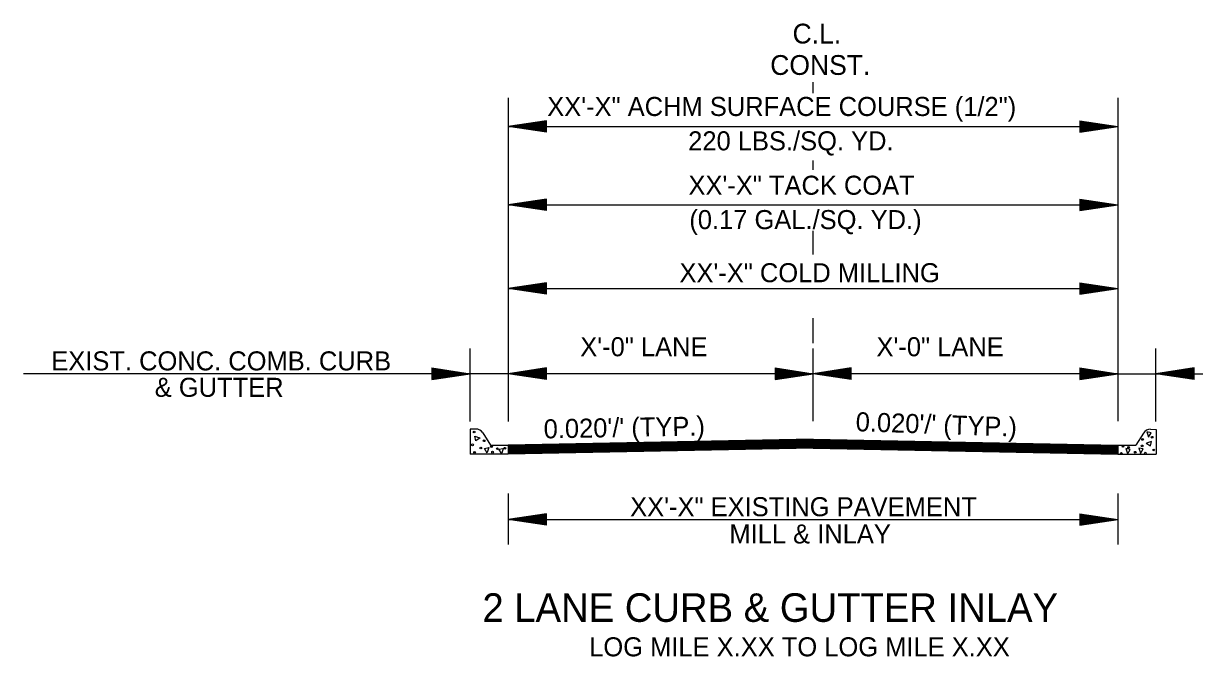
# Model space of a CAD drawing. Extents: x 542112 to 1930787, y -1968972 to 596640.
# Drawn here: x 546672.7 to 547133.6, y -1955910.7 to -1955661.3 of the extents above; entities that cross this region are included whole.
import ezdxf

# ---------------------------------------------------------------- set-up
doc = ezdxf.new("R2010")
doc.units = 0
doc.layers.add('R_Draft', color=7, linetype='Continuous')

msp = doc.modelspace()

# ---------------------------------------------------------------- linework, layer by layer
at = {"layer": 'R_Draft'}
for p, q in [((546983.53, -1955688.78), (546983.53, -1955684.37)), ((546863.53, -1955690.63), (546863.53, -1955818.05)), ((546878.53, -1955699.64), (546863.53, -1955701.89)), ((546863.53, -1955701.89), (547103.46, -1955701.89)), ((546878.53, -1955704.14), (546863.53, -1955701.89)), ((546878.53, -1955700.01), (546866.03, -1955701.89)), ((546878.53, -1955703.76), (546866.03, -1955701.89)), ((546878.53, -1955700.39), (546868.61, -1955701.89)), ((546878.53, -1955703.38), (546868.61, -1955701.89)), ((546878.53, -1955700.77), (546871.11, -1955701.89)), ((546878.53, -1955703), (546871.11, -1955701.89)), ((546878.53, -1955701.15), (546873.65, -1955701.89)), ((546878.53, -1955702.61), (546873.65, -1955701.89)), ((546878.53, -1955701.53), (546876.16, -1955701.89)), ((546878.53, -1955702.24), (546876.16, -1955701.89)), ((546878.53, -1955704.14), (546878.53, -1955699.64)), ((547088.46, -1955699.64), (547103.46, -1955701.89)), ((547088.46, -1955699.64), (547088.46, -1955704.14)), ((547088.46, -1955700.01), (547100.95, -1955701.89)), ((547088.46, -1955700.39), (547098.37, -1955701.89)), ((547088.46, -1955700.77), (547095.87, -1955701.89)), ((547088.46, -1955701.16), (547093.33, -1955701.89)), ((547088.46, -1955701.53), (547090.83, -1955701.89)), ((547088.46, -1955704.14), (547103.46, -1955701.89)), ((547088.46, -1955702.62), (547093.33, -1955701.89)), ((547088.46, -1955703.38), (547098.37, -1955701.89)), ((547088.46, -1955703.76), (547100.95, -1955701.89)), ((547088.46, -1955703), (547095.87, -1955701.89)), ((547088.46, -1955702.24), (547090.83, -1955701.89)), ((546983.53, -1955718.91), (546983.53, -1955715.24)), ((546878.53, -1955730.51), (546863.53, -1955732.76)), ((546878.53, -1955735.01), (546878.53, -1955730.51)), ((547088.46, -1955730.51), (547103.46, -1955732.76)), ((547088.46, -1955730.51), (547088.46, -1955735.01)), ((546863.53, -1955732.76), (547103.46, -1955732.76)), ((546878.53, -1955735.01), (546863.53, -1955732.76)), ((546878.53, -1955730.88), (546866.03, -1955732.76)), ((546878.53, -1955734.63), (546866.03, -1955732.76)), ((546878.53, -1955731.26), (546868.61, -1955732.76)), ((546878.53, -1955734.25), (546868.61, -1955732.76)), ((546878.53, -1955731.64), (546871.11, -1955732.76)), ((546878.53, -1955733.87), (546871.11, -1955732.76)), ((546878.53, -1955732.02), (546873.65, -1955732.76)), ((546878.53, -1955733.48), (546873.65, -1955732.76)), ((546878.53, -1955732.4), (546876.16, -1955732.76)), ((546878.53, -1955733.11), (546876.16, -1955732.76)), ((547088.46, -1955730.88), (547100.95, -1955732.76)), ((547088.46, -1955731.26), (547098.37, -1955732.76)), ((547088.46, -1955731.64), (547095.87, -1955732.76)), ((547088.46, -1955732.03), (547093.33, -1955732.76)), ((547088.46, -1955732.4), (547090.83, -1955732.76)), ((547088.46, -1955735.01), (547103.46, -1955732.76)), ((547088.46, -1955733.49), (547093.33, -1955732.76)), ((547088.46, -1955734.25), (547098.37, -1955732.76)), ((547088.46, -1955734.63), (547100.95, -1955732.76)), ((547088.46, -1955733.87), (547095.87, -1955732.76)), ((547088.46, -1955733.11), (547090.83, -1955732.76)), ((546983.53, -1955752.27), (546983.53, -1955742.97)), ((546878.53, -1955763.44), (546863.53, -1955765.69)), ((546863.53, -1955765.69), (547103.46, -1955765.69)), ((546878.53, -1955767.94), (546863.53, -1955765.69)), ((546878.53, -1955763.81), (546866.03, -1955765.69)), ((546878.53, -1955767.56), (546866.03, -1955765.69)), ((546878.53, -1955764.19), (546868.61, -1955765.69)), ((546878.53, -1955767.18), (546868.61, -1955765.69)), ((546878.53, -1955764.57), (546871.11, -1955765.69)), ((546878.53, -1955766.8), (546871.11, -1955765.69)), ((546878.53, -1955764.95), (546873.65, -1955765.69)), ((546878.53, -1955766.41), (546873.65, -1955765.69)), ((546878.53, -1955765.33), (546876.16, -1955765.69)), ((546878.53, -1955766.04), (546876.16, -1955765.69)), ((546878.53, -1955767.94), (546878.53, -1955763.44)), ((547088.46, -1955763.44), (547103.46, -1955765.69)), ((547088.46, -1955763.44), (547088.46, -1955767.94)), ((547088.46, -1955763.81), (547100.95, -1955765.69)), ((547088.46, -1955764.19), (547098.37, -1955765.69)), ((547088.46, -1955764.57), (547095.87, -1955765.69)), ((547088.46, -1955764.96), (547093.33, -1955765.69)), ((547088.46, -1955765.33), (547090.83, -1955765.69)), ((547088.46, -1955767.94), (547103.46, -1955765.69)), ((547088.46, -1955766.42), (547093.33, -1955765.69)), ((547088.46, -1955767.18), (547098.37, -1955765.69)), ((547088.46, -1955767.56), (547100.95, -1955765.69)), ((547088.46, -1955766.8), (547095.87, -1955765.69)), ((547088.46, -1955766.04), (547090.83, -1955765.69)), ((546983.53, -1955787.21), (546983.53, -1955777.34)), ((546848.53, -1955818.05), (546848.53, -1955789.33)), ((546983.53, -1955817.88), (546983.53, -1955789.33)), ((547118.46, -1955818.05), (547118.46, -1955789.33)), ((546863.53, -1955799.22), (546672.72, -1955799.22)), ((546833.52, -1955796.97), (546848.52, -1955799.22)), ((546833.52, -1955796.97), (546833.52, -1955801.47)), ((546833.52, -1955797.35), (546846.01, -1955799.22)), ((546833.52, -1955797.73), (546843.43, -1955799.22)), ((546833.52, -1955798.11), (546840.94, -1955799.22)), ((546833.52, -1955798.5), (546838.39, -1955799.22)), ((546833.52, -1955798.87), (546835.89, -1955799.22)), ((546833.52, -1955801.47), (546848.52, -1955799.22)), ((546833.52, -1955799.96), (546838.39, -1955799.22)), ((546833.52, -1955800.72), (546843.43, -1955799.22)), ((546833.52, -1955801.1), (546846.01, -1955799.22)), ((546833.52, -1955800.34), (546840.94, -1955799.22)), ((546833.52, -1955799.58), (546835.89, -1955799.22)), ((546878.53, -1955796.97), (546863.53, -1955799.22)), ((546983.53, -1955799.22), (546863.53, -1955799.22)), ((546878.53, -1955801.47), (546863.53, -1955799.22)), ((546878.53, -1955797.35), (546866.03, -1955799.22)), ((546878.53, -1955801.1), (546866.03, -1955799.22)), ((546878.53, -1955797.73), (546868.61, -1955799.22)), ((546878.53, -1955800.72), (546868.61, -1955799.22)), ((546878.53, -1955798.11), (546871.11, -1955799.22)), ((546878.53, -1955800.34), (546871.11, -1955799.22)), ((546878.53, -1955798.49), (546873.65, -1955799.22)), ((546878.53, -1955799.95), (546873.65, -1955799.22)), ((546878.53, -1955798.87), (546876.16, -1955799.22)), ((546878.53, -1955799.58), (546876.16, -1955799.22)), ((546878.53, -1955801.47), (546878.53, -1955796.97)), ((546968.53, -1955796.97), (546983.53, -1955799.22)), ((546968.53, -1955796.97), (546968.53, -1955801.47)), ((546968.53, -1955797.35), (546981.02, -1955799.22)), ((546968.53, -1955797.73), (546978.44, -1955799.22)), ((546968.53, -1955798.11), (546975.95, -1955799.22)), ((546968.53, -1955798.5), (546973.4, -1955799.22)), ((546968.53, -1955798.87), (546970.9, -1955799.22)), ((546968.53, -1955801.47), (546983.53, -1955799.22)), ((546968.53, -1955799.96), (546973.4, -1955799.22)), ((546968.53, -1955800.72), (546978.44, -1955799.22)), ((546968.53, -1955801.1), (546981.02, -1955799.22)), ((546968.53, -1955800.34), (546975.95, -1955799.22)), ((546968.53, -1955799.58), (546970.9, -1955799.22)), ((546998.53, -1955796.97), (546983.53, -1955799.22)), ((547103.46, -1955799.22), (546983.53, -1955799.22)), ((546998.53, -1955801.47), (546983.53, -1955799.22)), ((546998.53, -1955797.35), (546986.03, -1955799.22)), ((546998.53, -1955801.1), (546986.03, -1955799.22)), ((546998.53, -1955797.73), (546988.61, -1955799.22)), ((546998.53, -1955800.72), (546988.61, -1955799.22)), ((546998.53, -1955798.11), (546991.11, -1955799.22)), ((546998.53, -1955800.34), (546991.11, -1955799.22)), ((546998.53, -1955798.49), (546993.65, -1955799.22)), ((546998.53, -1955799.95), (546993.65, -1955799.22)), ((546998.53, -1955798.87), (546996.16, -1955799.22)), ((546998.53, -1955799.58), (546996.16, -1955799.22)), ((546998.53, -1955801.47), (546998.53, -1955796.97)), ((547088.46, -1955796.97), (547103.46, -1955799.22)), ((547088.46, -1955796.97), (547088.46, -1955801.47)), ((547088.46, -1955797.35), (547100.95, -1955799.22)), ((547088.46, -1955797.73), (547098.37, -1955799.22)), ((547088.46, -1955798.11), (547095.87, -1955799.22)), ((547088.46, -1955798.5), (547093.33, -1955799.22)), ((547088.46, -1955798.87), (547090.83, -1955799.22)), ((547088.46, -1955801.47), (547103.46, -1955799.22)), ((547088.46, -1955799.96), (547093.33, -1955799.22)), ((547088.46, -1955800.72), (547098.37, -1955799.22)), ((547088.46, -1955801.1), (547100.95, -1955799.22)), ((547088.46, -1955800.34), (547095.87, -1955799.22)), ((547088.46, -1955799.58), (547090.83, -1955799.22)), ((547103.46, -1955799.22), (547300.14, -1955799.22)), ((547133.46, -1955796.97), (547118.46, -1955799.22)), ((547133.46, -1955801.47), (547118.46, -1955799.22)), ((547133.46, -1955797.35), (547120.96, -1955799.22)), ((547133.46, -1955801.1), (547120.96, -1955799.22)), ((547133.46, -1955797.73), (547123.54, -1955799.22)), ((547133.46, -1955800.72), (547123.54, -1955799.22)), ((547133.46, -1955798.11), (547126.04, -1955799.22)), ((547133.46, -1955800.34), (547126.04, -1955799.22)), ((547133.46, -1955798.49), (547128.58, -1955799.22)), ((547133.46, -1955799.95), (547128.58, -1955799.22)), ((547133.46, -1955798.87), (547131.09, -1955799.22)), ((547133.46, -1955799.58), (547131.09, -1955799.22)), ((547133.46, -1955801.47), (547133.46, -1955796.97)), ((546850.69, -1955821.04), (546848.53, -1955821.08)), ((546848.53, -1955821.08), (546848.53, -1955830.93)), ((546853.51, -1955822.54), (546856.61, -1955827.44)), ((547113.5, -1955822.63), (547110.47, -1955827.43)), ((547116.32, -1955821.13), (547118.48, -1955821.17)), ((547118.48, -1955821.17), (547118.48, -1955830.93)), ((546983.53, -1955825.04), (546863.53, -1955827.44)), ((546983.53, -1955825.34), (546863.53, -1955827.74)), ((546983.53, -1955825.64), (546863.53, -1955828.04)), ((546983.53, -1955825.94), (546863.53, -1955828.34)), ((546983.53, -1955826.24), (546863.53, -1955828.64)), ((546983.53, -1955826.54), (546863.53, -1955828.94)), ((546983.53, -1955826.84), (546863.53, -1955829.24)), ((546983.53, -1955827.14), (546863.53, -1955829.54)), ((546983.53, -1955825.04), (547103.46, -1955827.43)), ((546983.53, -1955825.34), (547103.46, -1955827.73)), ((546983.53, -1955825.64), (547103.46, -1955828.03)), ((546983.53, -1955825.94), (547103.46, -1955828.33)), ((546983.53, -1955826.24), (547103.46, -1955828.63)), ((546983.53, -1955826.54), (547103.46, -1955828.93)), ((546983.53, -1955826.84), (547103.46, -1955829.23)), ((546983.53, -1955827.14), (547103.46, -1955829.53)), ((546863.53, -1955830.93), (546848.53, -1955830.93)), ((546856.61, -1955827.44), (546863.53, -1955827.44)), ((546863.53, -1955827.44), (546863.53, -1955830.93)), ((546983.53, -1955827.44), (546863.53, -1955829.84)), ((546983.53, -1955827.74), (546863.53, -1955830.14)), ((546983.53, -1955828.04), (546863.53, -1955830.44)), ((546983.53, -1955828.34), (546863.53, -1955830.74)), ((546983.53, -1955828.53), (546863.53, -1955830.93)), ((546983.53, -1955827.44), (547103.46, -1955829.83)), ((546983.53, -1955827.74), (547103.46, -1955830.13)), ((546983.53, -1955828.04), (547103.46, -1955830.43)), ((546983.53, -1955828.34), (547103.46, -1955830.73)), ((546983.53, -1955828.53), (547103.46, -1955830.93)), ((547103.46, -1955827.43), (547110.47, -1955827.43)), ((547103.46, -1955827.43), (547103.46, -1955830.93)), ((547103.46, -1955830.93), (547118.48, -1955830.93)), ((546863.53, -1955846.44), (546863.53, -1955866.44)), ((547103.46, -1955846.44), (547103.46, -1955866.44)), ((546878.53, -1955854.44), (546863.53, -1955856.69)), ((546878.53, -1955854.81), (546866.03, -1955856.69)), ((546878.53, -1955858.94), (546878.53, -1955854.44)), ((547088.46, -1955854.44), (547103.46, -1955856.69)), ((547088.46, -1955854.44), (547088.46, -1955858.94)), ((547088.46, -1955854.81), (547100.95, -1955856.69)), ((546863.53, -1955856.69), (547103.46, -1955856.69)), ((546878.53, -1955858.94), (546863.53, -1955856.69)), ((546878.53, -1955858.56), (546866.03, -1955856.69)), ((546878.53, -1955855.19), (546868.61, -1955856.69)), ((546878.53, -1955858.18), (546868.61, -1955856.69)), ((546878.53, -1955855.57), (546871.11, -1955856.69)), ((546878.53, -1955857.8), (546871.11, -1955856.69)), ((546878.53, -1955855.95), (546873.65, -1955856.69)), ((546878.53, -1955857.41), (546873.65, -1955856.69)), ((546878.53, -1955856.33), (546876.16, -1955856.69)), ((546878.53, -1955857.04), (546876.16, -1955856.69)), ((547088.46, -1955855.19), (547098.37, -1955856.69)), ((547088.46, -1955855.57), (547095.87, -1955856.69)), ((547088.46, -1955855.96), (547093.33, -1955856.69)), ((547088.46, -1955856.33), (547090.83, -1955856.69)), ((547088.46, -1955858.94), (547103.46, -1955856.69)), ((547088.46, -1955857.42), (547093.33, -1955856.69)), ((547088.46, -1955858.18), (547098.37, -1955856.69)), ((547088.46, -1955858.56), (547100.95, -1955856.69)), ((547088.46, -1955857.8), (547095.87, -1955856.69)), ((547088.46, -1955857.04), (547090.83, -1955856.69))]:
    msp.add_line(p, q, dxfattribs=at)
for points in [[(547103.46, -1955690.63), (547103.46, -1955817.88)], [(547115.49, -1955824.29), (547116.62, -1955822.5), (547114.85, -1955822.13), (547115.49, -1955824.03)], [(546852.47, -1955824.5), (546850.71, -1955825.63), (546850.33, -1955823.86), (546852.23, -1955824.5)], [(547114.54, -1955826.53), (547116.3, -1955827.66), (547116.68, -1955825.89), (547114.77, -1955826.53)], [(546855.28, -1955830.48), (546854.15, -1955828.69), (546855.91, -1955828.32), (546855.28, -1955830.22)], [(546860.94, -1955830.8), (546859.8, -1955829.01), (546861.58, -1955828.65), (546860.94, -1955830.54)], [(547107.18, -1955830.9), (547108.31, -1955829.11), (547106.54, -1955828.74), (547107.18, -1955830.64)], [(547112.31, -1955830.66), (547113.44, -1955828.87), (547111.67, -1955828.51), (547112.31, -1955830.4)]]:
    msp.add_lwpolyline(points, dxfattribs=at)
for centre in [(546850.08, -1955822.21), (546849.46, -1955827.24), (546854.01, -1955825.65), (547113.16, -1955825.11), (547116.92, -1955824.24), (546850.28, -1955830.22), (546852.75, -1955828.51), (546856.94, -1955827.98), (546857.35, -1955830.14), (546859.25, -1955828.76), (546862.18, -1955828.58), (547104.83, -1955830.61), (547105.47, -1955827.86), (547107.66, -1955828.28), (547110.3, -1955830.17), (547113, -1955827.67), (547114.26, -1955830.53), (547117.55, -1955829.26)]:
    msp.add_circle(centre, 0.339, dxfattribs=at)
for centre, start, end in [((546850.75, -1955824.3), 32.2756, 91.1196), ((547116.26, -1955824.39), 88.8804, 147.7244)]:
    msp.add_arc(centre, 3.26, start, end, dxfattribs=at)

# ---------------------------------------------------------------- texts
for s, height, p in [('C.L.', 7.8, (546975.43, -1955669.17)), ('CONST.', 7.8, (546966.64, -1955681.54)), ('XX\'-X" ACHM SURFACE COURSE (1/2")', 7.5, (546878.87, -1955697.72)), ('220 LBS./SQ. YD. ', 7.5, (546934.35, -1955711.26)), ('XX\'-X" TACK COAT', 7.5, (546934.45, -1955728.74)), ('(0.17 GAL./SQ. YD.)', 7.5, (546934.8, -1955742.28)), ('XX\'-X" COLD MILLING', 7.5, (546930.91, -1955763.2)), ('X\'-0" LANE', 7.5, (546891.87, -1955792.36)), ('X\'-0" LANE', 7.5, (547008.46, -1955792.36)), ('EXIST. CONC. COMB. CURB', 7.5, (546683.69, -1955797.93)), ('& GUTTER ', 7.5, (546724.41, -1955808.34)), ('XX\'-X" EXISTING PAVEMENT', 7.5, (546911.51, -1955855.37)), ('MILL & INLAY', 7.5, (546950.57, -1955866.09)), ('2 LANE CURB & GUTTER INLAY', 11.25, (546853.37, -1955896.97)), ('LOG MILE X.XX TO LOG MILE X.XX', 7.5, (546895.39, -1955910.55))]:
    msp.add_text(s, height=height, dxfattribs=at).set_placement(p)
for rotation, p in [(1.0984, (546877.53, -1955824.74)), (358.0646, (547000.17, -1955821.85))]:
    msp.add_text("0.020'/' (TYP.)", height=7.5, rotation=rotation, dxfattribs=at).set_placement(p)

doc.saveas('drawing.dxf')
